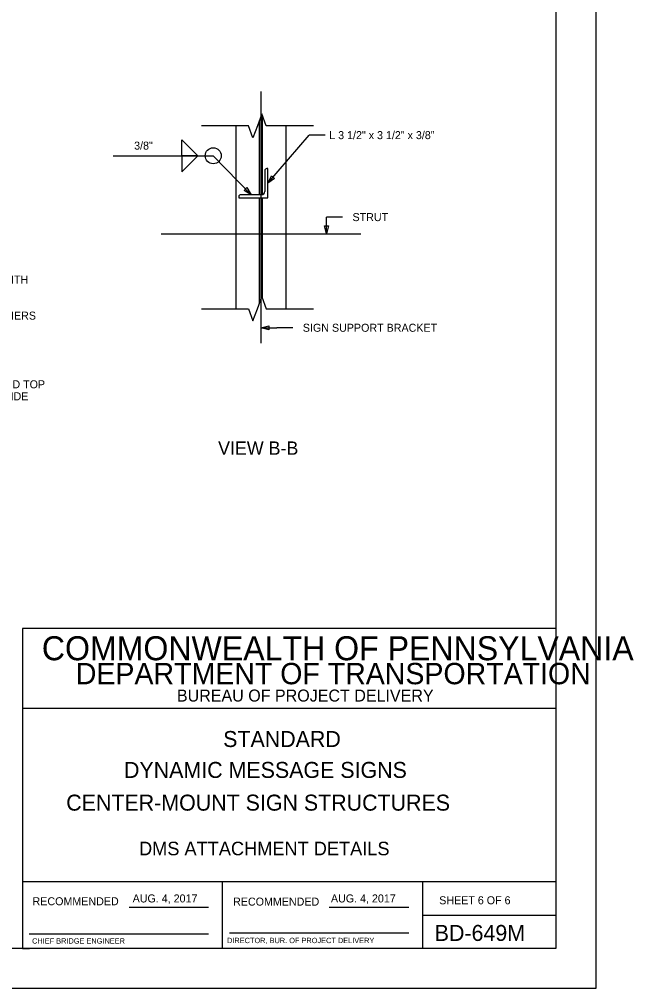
# Model space of a CAD drawing. Extents: x 3829340 to 3831660, y 499389 to 501171.
# Drawn here: x 3830805.8 to 3831036.2, y 499389.2 to 499752.6 of the extents above; entities that cross this region are included whole.
import ezdxf

# ---------------------------------------------------------------- set-up
doc = ezdxf.new("R2010")
doc.units = 0
for name, color, linetype in [('10', 7, 'Continuous'), ('2', 7, 'Continuous'), ('CNTR', 7, 'Continuous'), ('Default', 7, 'Continuous'), ('DIM TXT', 7, 'Continuous'), ('PLT-BNDY', 7, 'Continuous'), ('structure', 7, 'Continuous')]:
    doc.layers.add(name, color=color, linetype=linetype)

msp = doc.modelspace()

# ---------------------------------------------------------------- linework, layer by layer
at = {"layer": '2'}
for p, q in [((3831006.96, 499968.19), (3831006.96, 499404.19)), ((3831006.96, 499524.19), (3830806.96, 499524.19)), ((3830806.96, 499524.19), (3830806.96, 499404.19)), ((3831006.96, 499494.19), (3830806.96, 499494.19)), ((3831006.96, 499429.19), (3830806.96, 499429.19)), ((3830881.96, 499404.19), (3830881.96, 499429.19)), ((3830956.96, 499429.19), (3830956.96, 499404.19)), ((3830846.93, 499419.69), (3830876.69, 499419.69)), ((3830921.93, 499419.69), (3830951.83, 499419.69)), ((3830956.96, 499416.69), (3831006.96, 499416.69)), ((3830809.46, 499409.69), (3830876.69, 499409.69)), ((3830884.59, 499410.06), (3830951.83, 499410.06)), ((3831006.96, 499404.19), (3830220.96, 499404.19)), ((3830806.96, 499404.19), (3830809.53, 499404.19))]:
    msp.add_line(p, q, dxfattribs=at)
at = {"layer": 'CNTR'}
for p, q in [((3830896.42, 499725.6), (3830896.42, 499631.22)), ((3830858.92, 499672.22), (3830933.92, 499672.22))]:
    msp.add_line(p, q, dxfattribs=at)
at = {"layer": 'DIM TXT'}
for p, q in [((3830896.76, 499717.21), (3830895.09, 499712.7)), ((3830898.42, 499712.7), (3830896.76, 499717.21)), ((3830891.76, 499712.7), (3830874.07, 499712.7)), ((3830893.42, 499708.19), (3830891.76, 499712.7)), ((3830895.09, 499712.7), (3830893.42, 499708.19)), ((3830916.1, 499712.7), (3830898.42, 499712.7)), ((3830899.01, 499691.16), (3830914.52, 499709.2)), ((3830920.52, 499709.2), (3830914.52, 499709.2)), ((3830866.74, 499707.47), (3830872.74, 499701.48)), ((3830866.74, 499701.48), (3830866.74, 499707.47)), ((3830841, 499701.48), (3830878.5, 499701.48)), ((3830872.74, 499701.48), (3830866.74, 499701.48)), ((3830866.74, 499695.48), (3830872.74, 499701.48)), ((3830872.74, 499701.48), (3830866.74, 499701.48)), ((3830866.74, 499701.48), (3830866.74, 499695.48)), ((3830892.71, 499686.87), (3830878.5, 499701.48)), ((3830921.05, 499672.22), (3830921.05, 499678.47)), ((3830927.05, 499678.47), (3830921.05, 499678.47)), ((3830895.09, 499644.09), (3830896.76, 499648.61)), ((3830896.76, 499648.61), (3830898.42, 499644.09)), ((3830874.07, 499644.09), (3830891.76, 499644.09)), ((3830891.76, 499644.09), (3830893.42, 499639.58)), ((3830893.42, 499639.58), (3830895.09, 499644.09)), ((3830898.42, 499644.09), (3830916.1, 499644.09)), ((3830896.42, 499636.92), (3830902.42, 499636.92)), ((3830908.42, 499636.92), (3830902.42, 499636.92))]:
    msp.add_line(p, q, dxfattribs=at)
for points in [[(3830901.54, 499692.95), (3830899.01, 499691.16), (3830900.4, 499693.93)], [(3830891.15, 499689.54), (3830892.71, 499686.87), (3830890.08, 499688.49)], [(3830921.8, 499675.22), (3830921.05, 499672.22), (3830920.3, 499675.22)], [(3830899.42, 499636.17), (3830896.42, 499636.92), (3830899.42, 499637.67)]]:
    msp.add_lwpolyline(points, close=True, dxfattribs=at)
msp.add_circle((3830878.5, 499701.48), 3, dxfattribs=at)
at = {"layer": 'PLT-BNDY'}
msp.add_lwpolyline([(3830180.96, 499983.19), (3831021.96, 499983.19), (3831021.96, 499389.19), (3830180.96, 499389.19)], close=True, dxfattribs=at)
at = {"layer": 'structure'}
for p, q in [((3830896.95, 499686.9), (3830896.95, 499716.38)), ((3830887.06, 499685.7), (3830887.06, 499712.7)), ((3830895.88, 499686.87), (3830895.88, 499714.35)), ((3830905.78, 499712.7), (3830905.78, 499644.09)), ((3830887.06, 499644.09), (3830887.06, 499685.7)), ((3830895.88, 499646.24), (3830895.88, 499685.7)), ((3830896.95, 499648.46), (3830896.95, 499685.7))]:
    msp.add_line(p, q, dxfattribs=at)
for points in [[(3830897.84, 499695.85), (3830897.84, 499688.04)], [(3830899.01, 499685.7), (3830899.01, 499696.63), (3830898.62, 499696.63)], [(3830896.67, 499686.87), (3830888.86, 499686.87)], [(3830888.07, 499686.08), (3830888.07, 499685.7), (3830899.01, 499685.7)]]:
    msp.add_lwpolyline(points, dxfattribs=at)
for centre, radius, start, end in [((3830898.62, 499695.85), 0.785, 90, 180), ((3830888.86, 499686.08), 0.785, 90, 180), ((3830896.67, 499688.04), 1.17, 270, 0)]:
    msp.add_arc(centre, radius, start, end, dxfattribs=at)

# ---------------------------------------------------------------- texts
at = {"layer": '10'}
for s, height, p in [('STANDARD ', 6, (3830882.23, 499479.77)), ('DYNAMIC MESSAGE SIGNS', 6, (3830845.03, 499468.18)), ('CENTER-MOUNT SIGN STRUCTURES', 6, (3830823.36, 499455.92)), ('DMS ATTACHMENT DETAILS', 5.1, (3830850.67, 499439.17))]:
    msp.add_text(s, height=height, dxfattribs=at).set_placement(p)
at = {"layer": '2'}
for s, height, p in [('COMMONWEALTH OF PENNSYLVANIA', 9, (3830814.21, 499512.31)), ('DEPARTMENT OF TRANSPORTATION', 8.0002, (3830826.96, 499503.31)), ('BUREAU OF PROJECT DELIVERY', 4.5, (3830864.88, 499496.82)), ('RECOMMENDED', 3, (3830810.73, 499420.44)), ('RECOMMENDED', 3, (3830885.95, 499420.31))]:
    msp.add_text(s, height=height, rotation=360, dxfattribs=at).set_placement(p)
for s, height, p in [('AUG. 4, 2017', 3, (3830848.27, 499421.5)), ('AUG. 4, 2017', 3, (3830922.66, 499421.5)), ('SHEET 6 OF 6', 3, (3830963.27, 499420.81)), ('BD-649M', 6, (3830961.59, 499407.06)), ('CHIEF BRIDGE ENGINEER', 2.0002, (3830810.55, 499406.06)), ('  DIRECTOR, BUR. OF PROJECT DELIVERY', 2.0002, (3830882.15, 499406.24))]:
    msp.add_text(s, height=height, dxfattribs=at).set_placement(p)
at = {"layer": 'Default'}
msp.add_text('VIEW B-B', height=5, dxfattribs=at).set_placement((3830880.33, 499589.36))
at = {"layer": 'DIM TXT'}
for s, height, p in [('L 3 1/2" x 3 1/2" x 3/8"', 2.9999, (3830922.02, 499707.7)), ('3/8"', 3, (3830848.83, 499703.77)), ('  STRUT', 3, (3830928.53, 499676.97)), ('GALVANIZED OR STAINLESS WITH', 2.9999, (3830742.03, 499653.53)), ('GALVANIZED STANDARD WASHERS', 2.9999, (3830742.03, 499640.03)), ('  SIGN SUPPORT BRACKET', 2.9999, (3830909.89, 499635.48)), ('BETWEEN ANGLE AND TOP ', 2.9999, (3830761.93, 499614.28)), ('OF CHORD TO PROVIDE ', 2.9999, (3830761.93, 499609.78))]:
    msp.add_text(s, height=height, dxfattribs=at).set_placement(p)

doc.saveas('drawing.dxf')
